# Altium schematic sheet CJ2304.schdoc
size 127 x 101 mm
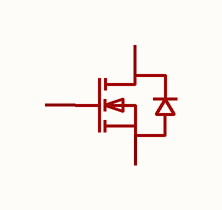
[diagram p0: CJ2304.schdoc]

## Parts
Q?  cj2304  [SOT-23-3_L2.9-W1.3-P1.90-LS2.4-BR]  (value not drawn)

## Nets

Not connected (* = marked no-connect by the designer): Q? 1(G) 2(S) 3(D)

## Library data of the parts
Q? = cj2304: 数量:1个N沟道;漏源电压(Vdss):30V;连续漏极电流(Id):3.3A;导通电阻(RDS(on)):60mΩ@10V;耗散功率(Pd):350mW;阈值电压(Vgs(th)):1V;; Manufacturer: CJ(江苏长电/长晶); AddInBom: yes; ModelId: c62791f0466c4ae2a892c056b845b0ca; ModelName: SOT-23-3P_L2.9-W1.3-H1.0-LS2.4-P0.95; ModelTransform: 98.425,114.173,0,180,0,0,0.0005,-0.0005,0; Number: 1个N沟道; Drain to Source Voltage: 30V; Current - Continuous Drain(Id): 3.3A; Pd - Power Dissipation: 350mW; Gate Threshold Voltage (Vgs(th)): 1V; Gate Charge(Qg): 3.2nC@10V; Input Capacitance(Ciss): 235pF; Reverse Transfer Capacitance (Crss@Vds): 17pF; Type: N沟道; Output Capacitance(Coss): 45pF; Vgs: ±20V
